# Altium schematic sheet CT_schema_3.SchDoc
size 430 x 328 mm
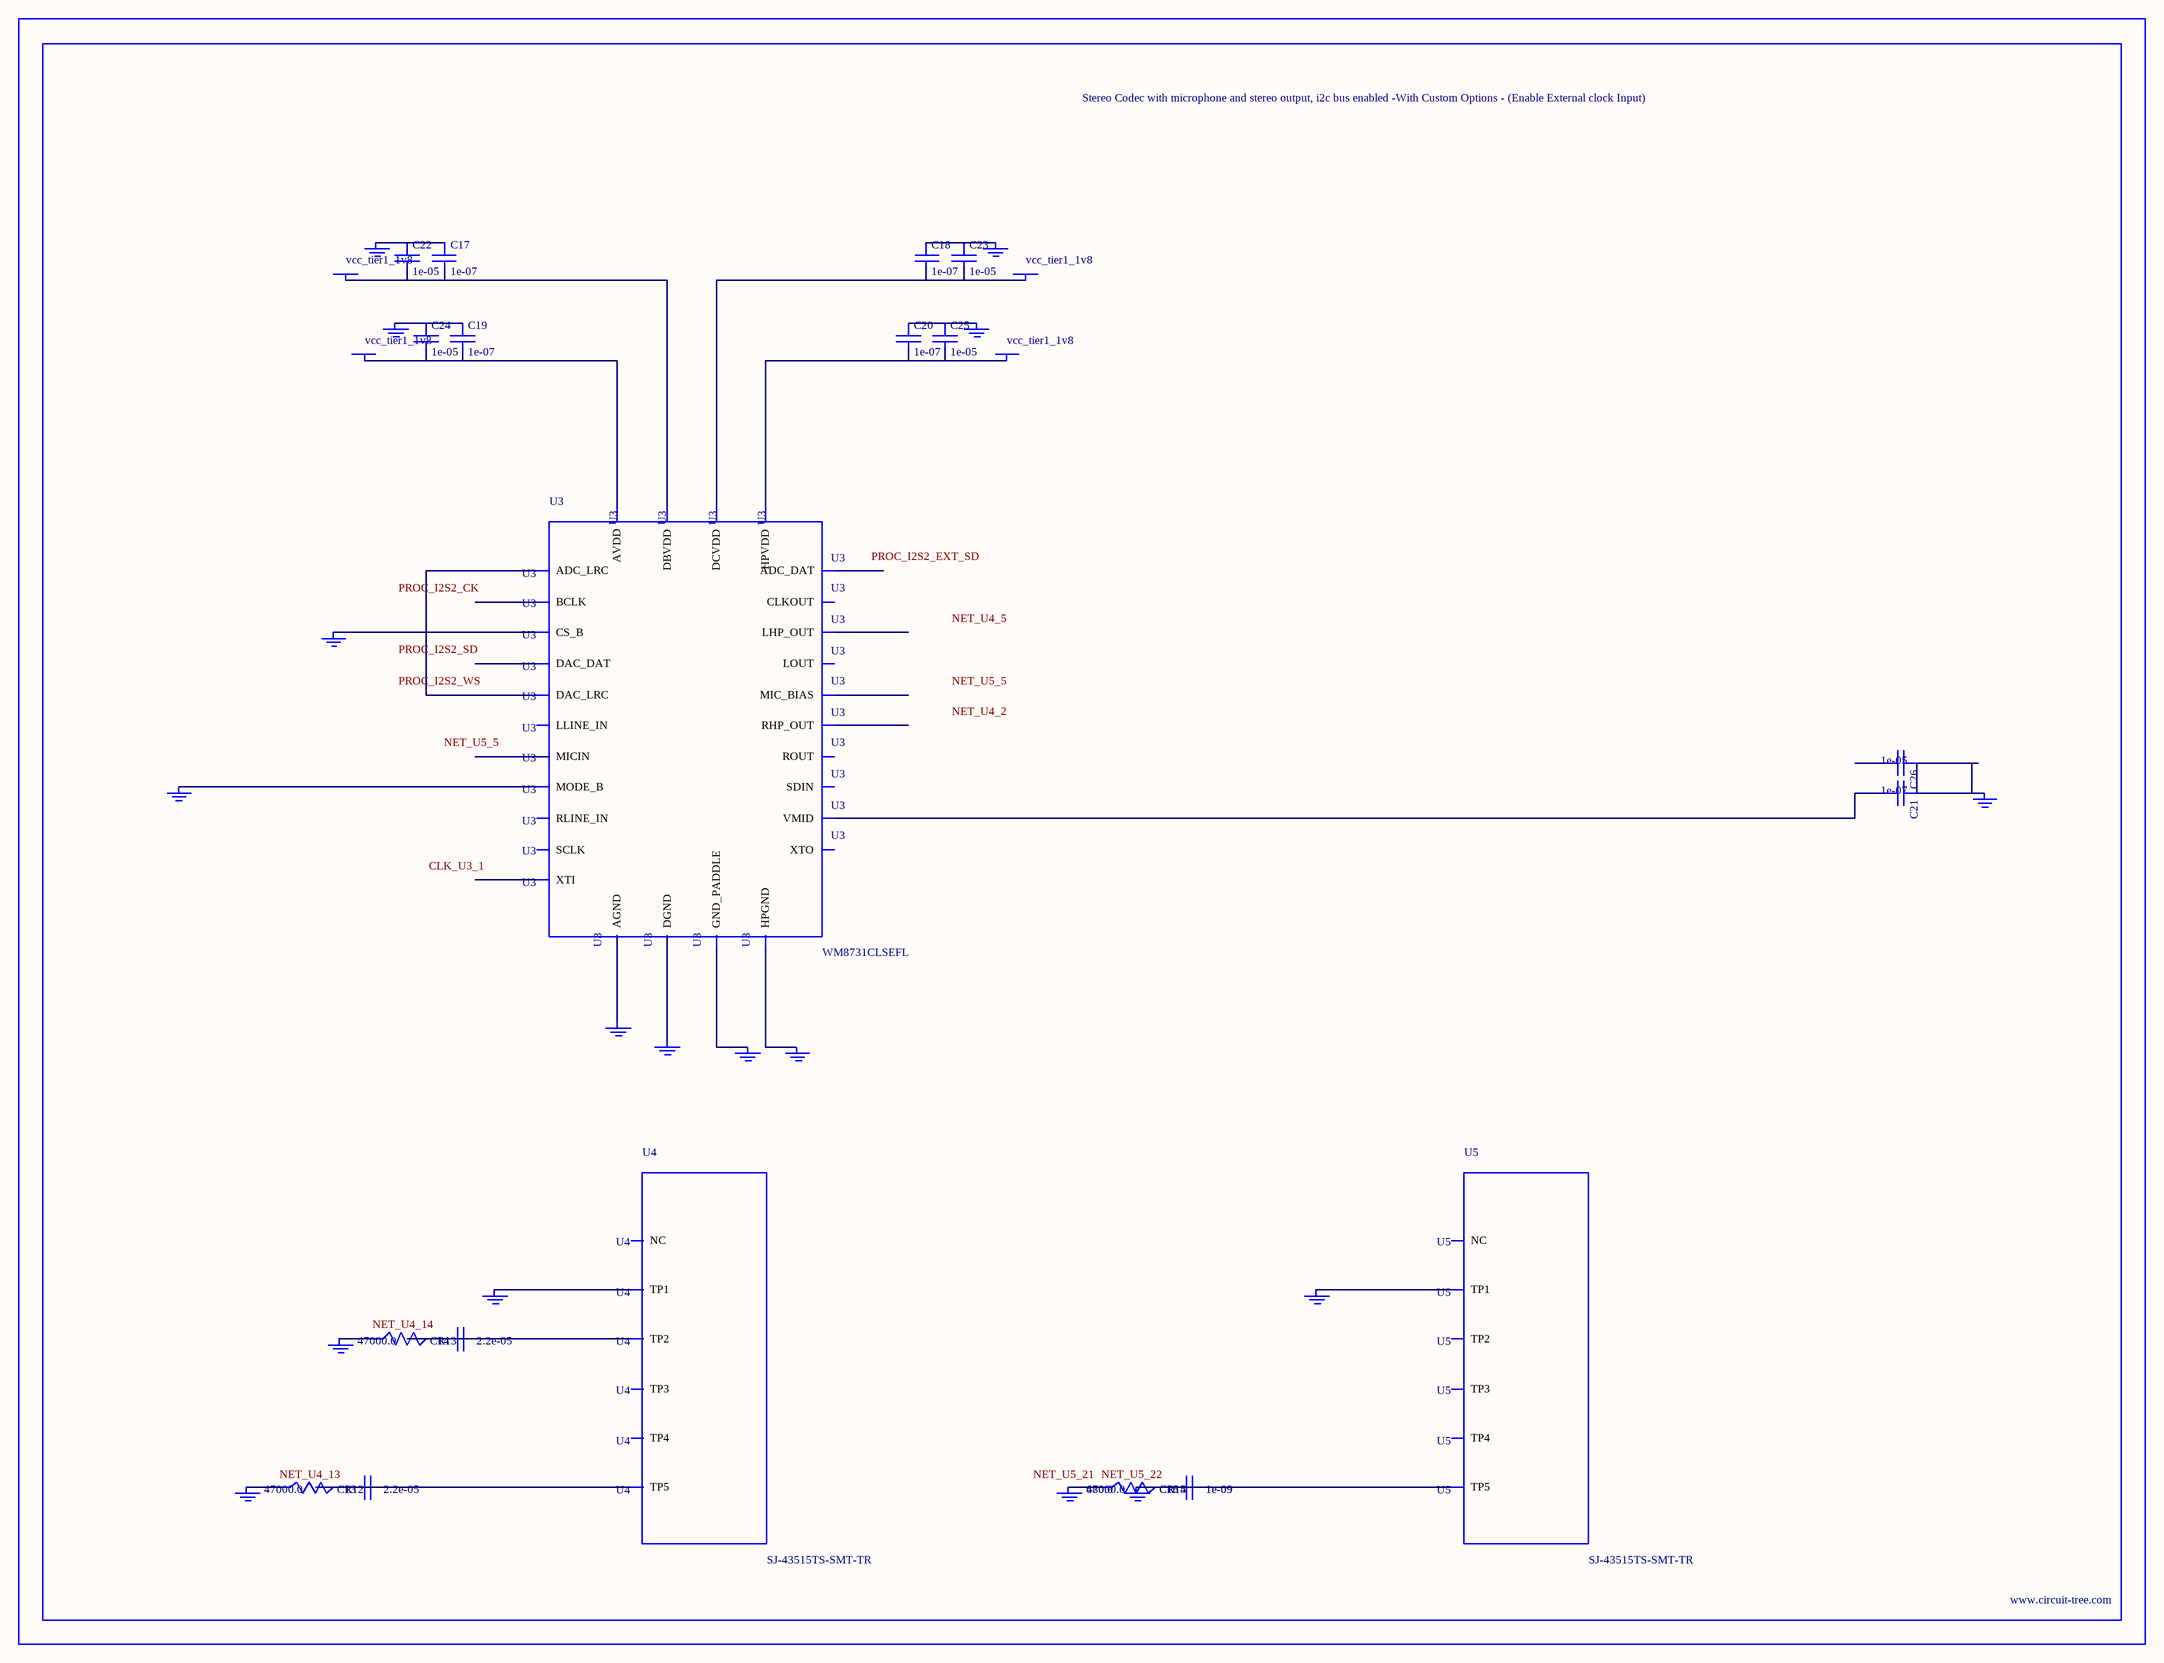
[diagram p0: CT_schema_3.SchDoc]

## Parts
BORDER2  (no value)
C13  2.2e-05  [C1210]
C14  2.2e-05  [C1210]
C15  1e-09  [C0402]
C16  1e-09  [C0402]
C17  1e-07  [C0402]
C18  1e-07  [C0402]
C19  1e-07  [C0402]
C20  1e-07  [C0402]
C21  1e-07  [C0402]
C22  1e-05  [C0805]
C23  1e-05  [C0805]
C24  1e-05  [C0805]
C25  1e-05  [C0805]
C26  1e-05  [C0805]
GND_INSTANCE_2_0  (no value)
GND_INSTANCE_2_1  (no value)
GND_INSTANCE_2_2  (no value)
GND_INSTANCE_2_3  (no value)
GND_INSTANCE_2_4  (no value)
GND_INSTANCE_2_5  (no value)
GND_INSTANCE_2_6  (no value)
GND_INSTANCE_2_7  (no value)
GND_INSTANCE_2_8  (no value)
GND_INSTANCE_2_9  (no value)
GND_INSTANCE_2_10  (no value)
GND_INSTANCE_2_11  (no value)
GND_INSTANCE_2_12  (no value)
GND_INSTANCE_2_13  (no value)
GND_INSTANCE_2_14  (no value)
GND_INSTANCE_2_15  (no value)
GND_INSTANCE_2_16  (no value)
POWER_INSTANCE_2_0  vcc_tier1_1v8
POWER_INSTANCE_2_1  vcc_tier1_1v8
POWER_INSTANCE_2_2  vcc_tier1_1v8
POWER_INSTANCE_2_3  vcc_tier1_1v8
R12  47000.0  [R0603]
R13  47000.0  [R0603]
R14  47000.0  [R0603]
R15  680.0  [R0603]
U3  WM8731CLSEFL  [QFN-28]
U4  SJ-43515TS-SMT-TR  [SJ-43515TS-SMT-TR]
U5  SJ-43515TS-SMT-TR  [SJ-43515TS-SMT-TR]

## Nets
NetC13_1: C13.1 C13.2 R12.2 U4.5(TP5)
NetC14_1: C14.1 C14.2 R13.2 U4.2(TP2)
NetC15_1: C15.1 C15.2 C16.1 C16.2 GND_INSTANCE_2_16.0(GND) R14.2 R15.2 U5.5(TP5)
NetC17_1: C17.1 C22.1 GND_INSTANCE_2_1.0(GND)
NetC17_2: C17.2 C22.2 POWER_INSTANCE_2_1.0(PWR) U3.5(DBVDD)
NetC18_1: C18.1 C23.1 GND_INSTANCE_2_0.0(GND)
NetC18_2: C18.2 C23.2 POWER_INSTANCE_2_0.0(PWR) U3.3(DCVDD)
NetC19_1: C19.1 C24.1 GND_INSTANCE_2_4.0(GND)
NetC19_2: C19.2 C24.2 POWER_INSTANCE_2_3.0(PWR) U3.18(AVDD)
NetC20_1: C20.1 C25.1 GND_INSTANCE_2_2.0(GND)
NetC20_2: C20.2 C25.2 POWER_INSTANCE_2_2.0(PWR) U3.12(HPVDD)
NetC21_1: C21.1 C26.1 GND_INSTANCE_2_5.0(GND)
NetC21_2: C21.2 U3.20(VMID)
NetGND_INSTANCE_2_3_0: GND_INSTANCE_2_3.0(GND) U3.15(HPGND)
NetGND_INSTANCE_2_6_0: GND_INSTANCE_2_6.0(GND) U3.25(MODE_B)
NetGND_INSTANCE_2_7_0: GND_INSTANCE_2_7.0(GND) U3.26(CS_B)
NetGND_INSTANCE_2_8_0: GND_INSTANCE_2_8.0(GND) U3.29(GND_PADDLE)
NetGND_INSTANCE_2_9_0: GND_INSTANCE_2_9.0(GND) U3.4(DGND)
NetGND_INSTANCE_2_10_0: GND_INSTANCE_2_10.0(GND) U3.19(AGND)
NetGND_INSTANCE_2_11_0: GND_INSTANCE_2_11.0(GND) U4.1(TP1)
NetGND_INSTANCE_2_12_0: GND_INSTANCE_2_12.0(GND) R13.1
NetGND_INSTANCE_2_13_0: GND_INSTANCE_2_13.0(GND) R12.1
NetGND_INSTANCE_2_14_0: GND_INSTANCE_2_14.0(GND) U5.1(TP1)
NetGND_INSTANCE_2_15_0: GND_INSTANCE_2_15.0(GND) R14.1 R15.1
NetU3_9: U3.9(DAC_LRC) U3.11(ADC_LRC)

Not connected (* = marked no-connect by the designer): C26 2; U3 1(XTI) 2(XTO) 6(CLKOUT) 7(BCLK) 8(DAC_DAT) 10(ADC_DAT) 13(LHP_OUT) 14(RHP_OUT) 16(LOUT) 17(ROUT) 21(MIC_BIAS) 22(MICIN) 23(RLINE_IN) 24(LLINE_IN) 27(SDIN) 28(SCLK); U4 3(TP3) 4(TP4) 6(NC); U5 2(TP2) 3(TP3) 4(TP4) 6(NC)

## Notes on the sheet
- Labels drawn without touching a wire or pin: CLK_U3_1, NET_U4_2, NET_U4_5, NET_U4_13, NET_U4_14, NET_U5_5, NET_U5_21, NET_U5_22, PROC_I2S2_CK, PROC_I2S2_EXT_SD, PROC_I2S2_SD, PROC_I2S2_WS

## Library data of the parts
BORDER2 = BORDER_PAGE2
C13 C14 = C1210C224K5RACTU
C15 C16 = C0402C102K3RAC
C17-C21 = C0402C104K3RACTU
C22-C26 = C0805C106K8RACTU
GND_INSTANCE_2_0-GND_INSTANCE_2_16 = GND
POWER_INSTANCE_2_0-POWER_INSTANCE_2_3 = PWR
R12-R14 = RC0603JR-0747KL
R15 = RC0603JR-07680RL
